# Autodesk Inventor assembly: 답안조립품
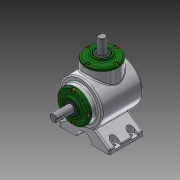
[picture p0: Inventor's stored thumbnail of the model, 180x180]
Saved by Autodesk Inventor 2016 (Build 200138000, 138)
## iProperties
Created: 2017-04
Part Number: 답안조립품
Material: 일반
Document SubType Name: Assembly
Designer: H
Author: H
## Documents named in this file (14)
- C:\Users\CAMTIC\Desktop\470407V1023\답안조립품.iam
- C:\Users\CAMTIC\Desktop\470407V1023\1-본체.ipt
- C:\Users\CAMTIC\Desktop\470407V1023\메인 베벨기어.ipt
- C:\Users\CAMTIC\Desktop\470407V1023\메인 축.ipt
- 메인 축.ipt
- C:\Users\CAMTIC\Desktop\470407V1023\베어링 6203.ipt
- C:\Users\CAMTIC\Desktop\470407V1023\볼트 M4.ipt
- C:\Users\CAMTIC\Desktop\470407V1023\서브 베벨기어.ipt
- C:\Users\CAMTIC\Desktop\470407V1023\서브 축.ipt
- 서브 축.ipt
- C:\Users\CAMTIC\Desktop\470407V1023\오일실 17 32 8.ipt
- C:\Users\CAMTIC\Desktop\470407V1023\커버.ipt
- C:\Users\CAMTIC\Desktop\470407V1023\키 4x4.ipt
- C:\Users\CAMTIC\Desktop\470407V1023\키 5x5.ipt
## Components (1 placed, 1 different names)
1. 1-본체:1
